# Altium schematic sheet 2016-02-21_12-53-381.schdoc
size 339 x 144 mm; SheetNumber: 1; SheetTotal: 1
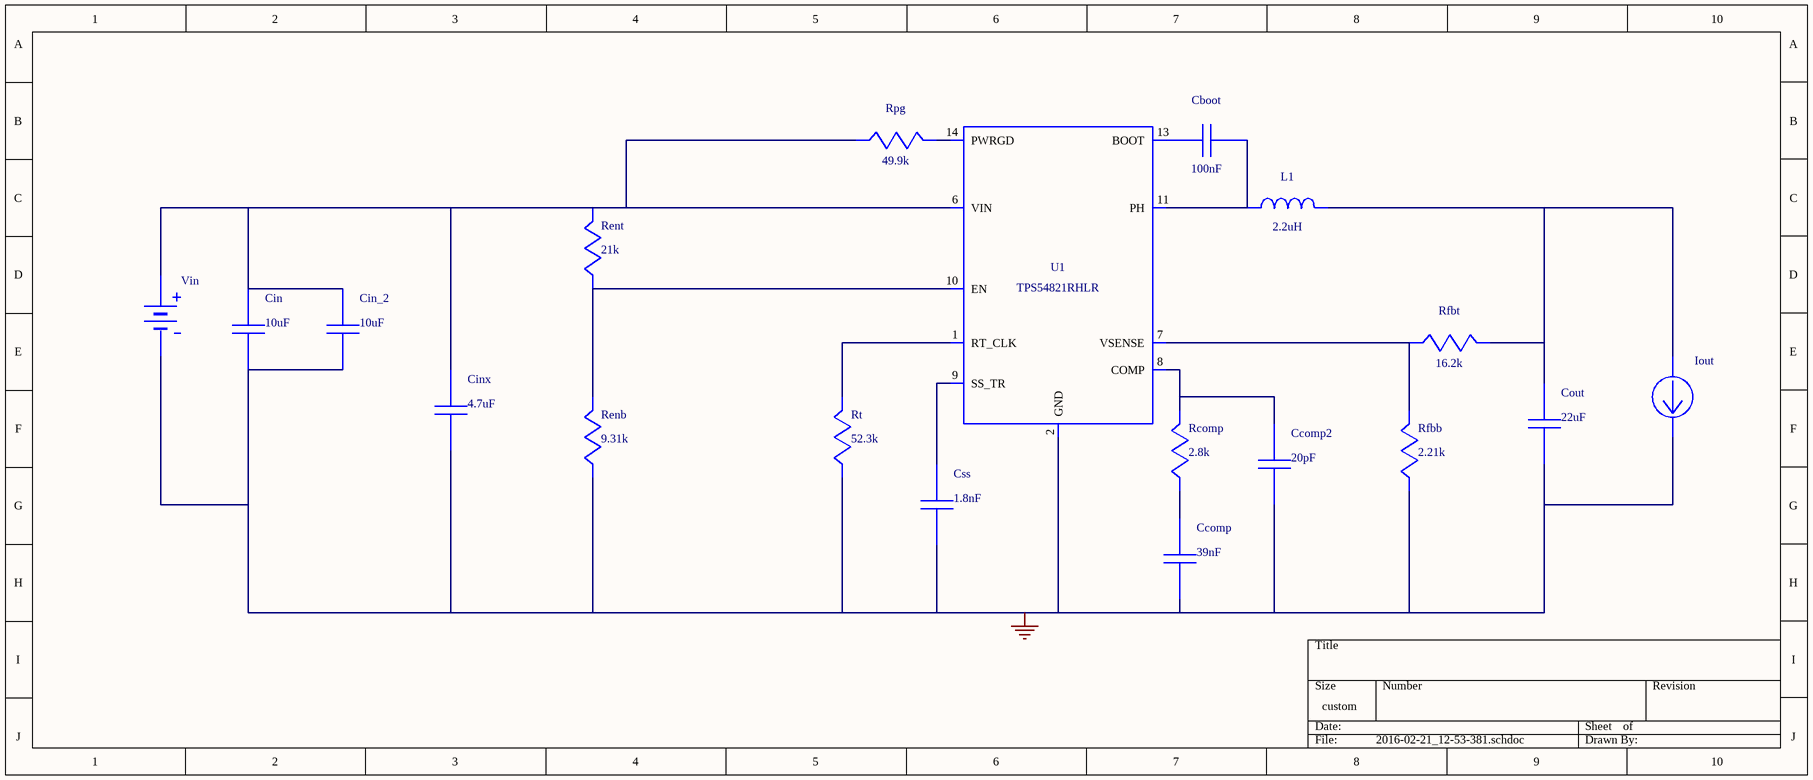
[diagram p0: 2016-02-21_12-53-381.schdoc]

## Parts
Cboot  value 100nF  (hidden comment: 08053C104KAT2A)
Ccomp  value 39nF  (hidden comment: GRM155R61A393KA01D)
Ccomp2  value 20pF  (hidden comment: CL21C200JBANNNC)
Cin  value 10uF  (hidden comment: GRM31CR61E106KA12L)
Cin_2  value 10uF  (hidden comment: GRM31CR61E106KA12L)
Cinx  value 4.7uF  (hidden comment: GRM21BR61E475KA12L)
Cout  value 22uF  (hidden comment: GRM31CR61A226KE19L)
Css  value 1.8nF  (hidden comment: GRM033R71A182KA01D)
Iout  WB_CURRENT_LOAD  (value not drawn)
L1  value 2.2uH  (hidden comment: XAL4020-222MEB)
Rcomp  value 2.8k  (hidden comment: CRCW04022K80FKED)
Renb  value 9.31k  (hidden comment: CRCW04029K31FKED)
Rent  value 21k  (hidden comment: CRCW040221K0FKED)
Rfbb  value 2.21k  (hidden comment: CRCW04022K21FKED)
Rfbt  value 16.2k  (hidden comment: CRCW040216K2FKED)
Rpg  value 49.9k  (hidden comment: CRCW040249K9FKED)
Rt  value 52.3k  (hidden comment: CRCW040252K3FKED)
U1  TPS54821RHLR
Vin  WB_BATTERY  (value not drawn)

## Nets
0: Ccomp.2 Ccomp2.2 Cin.2 Cin_2.2 Cinx.2 Cout.2 Css.2 Iout.2(-) Renb.2 Rfbb.2 Rt.2 U1.2(GND) U1.3(GND) U1.15(EPAD) Vin.2(-)
NetCboot_1: Cboot.1 U1.13(BOOT)
NetCboot_2: Cboot.2 L1.1 U1.11(PH) U1.12(PH)
NetCcomp2_1: Ccomp2.1 Rcomp.1 U1.8(COMP)
NetCcomp_1: Ccomp.1 Rcomp.2
NetCin_1: Cin.1 Cin_2.1 Cinx.1 Rent.1 Rpg.2 U1.4(PVIN) U1.5(PVIN) U1.6(VIN) Vin.1(+)
NetCout_1: Cout.1 Iout.1(+) L1.2 Rfbt.1
NetCss_1: Css.1 U1.9(SS_TR)
NetRenb_1: Renb.1 Rent.2 U1.10(EN)
NetRfbb_1: Rfbb.1 Rfbt.2 U1.7(VSENSE)
NetRpg_1: Rpg.1 U1.14(PWRGD)
NetRt_1: Rt.1 U1.1(RT_CLK)

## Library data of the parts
Cboot = 08053C104KAT2A: Manufacturer Name: AVX
Ccomp = GRM155R61A393KA01D: GRM155R61A393KA0; Manufacturer Name: MuRata
Ccomp2 = CL21C200JBANNNC: Manufacturer Name: Samsung Electro-Mechanics
Cin Cin_2 = GRM31CR61E106KA12L: GRM31CR61E106KA1; Manufacturer Name: MuRata
Cinx = GRM21BR61E475KA12L: GRM21BR61E475KA1; Manufacturer Name: MuRata
Cout = GRM31CR61A226KE19L: GRM31CR61A226KE1; Manufacturer Name: MuRata
Css = GRM033R71A182KA01D: GRM033R71A182KA0; Manufacturer Name: MuRata
Iout = WB_CURRENT_LOAD: Value: UNLISTED
L1 = XAL4020-222MEB: Manufacturer Name: Coilcraft
Rcomp = CRCW04022K80FKED: Manufacturer Name: Vishay-Dale
Renb = CRCW04029K31FKED: Manufacturer Name: Vishay-Dale
Rent = CRCW040221K0FKED: Manufacturer Name: Vishay-Dale
Rfbb = CRCW04022K21FKED: Manufacturer Name: Vishay-Dale
Rfbt = CRCW040216K2FKED: Manufacturer Name: Vishay-Dale
Rpg = CRCW040249K9FKED: Manufacturer Name: Vishay-Dale
Rt = CRCW040252K3FKED: Manufacturer Name: Vishay-Dale
U1 = TPS54821RHLR: Manufacturer Name: Texas Instruments; Value: UNLISTED
Vin = WB_BATTERY: Value: UNLISTED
